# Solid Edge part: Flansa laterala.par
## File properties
Author: ptcarter
Template: Ansimm.Par
Last saved by: Ionut
Revision: 47
Application: Solid Edge
Accuracy: 0.99
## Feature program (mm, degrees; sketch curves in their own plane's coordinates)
sketch for "ExtrudedProtrusion_1" plane through (0, 0, 0) normal (0, 0, 1) x-axis (1, 0, 0)
  line (-45, -35) -> (-45, 35)
  arc centre (-35, 35) radius 10 from (-45, 35) to (-35, 45) cw
  line (-35, 45) -> (35, 45)
  arc centre (35, 35) radius 10 from (35, 45) to (45, 35) cw
  line (45, 35) -> (45, -35)
  arc centre (35, -35) radius 10 from (45, -35) to (35, -45) cw
  line (35, -45) -> (-35, -45)
  arc centre (-35, -35) radius 10 from (-35, -45) to (-45, -35) cw
extrude "ExtrudedProtrusion_1" add finite 10 along +normal
sketch for "Hole_1" plane through (0, 0, 10) normal (0, 0, 1) x-axis (1, 0, 0)
  hole centre (-35, -35) bore radius 5
hole "Hole_1" through
sketch for "Hole_2" plane through (0, 0, 10) normal (0, 0, 1) x-axis (1, 0, 0)
  hole centre (-35, 35) bore radius 5
hole "Hole_2" through
sketch for "Hole_3" plane through (0, 0, 10) normal (0, 0, 1) x-axis (1, 0, 0)
  hole centre (35, 35) bore radius 5
hole "Hole_3" through
sketch for "Hole_4" plane through (0, 0, 10) normal (0, 0, 1) x-axis (1, 0, 0)
  hole centre (35, -35) bore radius 5
hole "Hole_4" nominal diameter 7.8125 through
pattern "unnamed Pattern 1" of "Hole_1", "Hole_2", "Hole_3", "Hole_4"
sketch for "unnamed Protrusion 1" plane through (0, 0, 10) normal (0, 0, 1) x-axis (1, 0, 0)
  line (-17.3205, -30) -> (17.3205, -30)
  line (17.3205, -30) -> (34.641, 0)
  line (34.641, 0) -> (17.3205, 30)
  line (17.3205, 30) -> (-17.3205, 30)
  line (-17.3205, 30) -> (-34.641, 0)
  line (-34.641, 0) -> (-17.3205, -30)
  dimension = 34.641
extrude "unnamed Protrusion 1" add finite 20 along +normal
fillet "Round_1" radius 4
fillet "Round_2" radius 2  Radii2 = 1.5 mm
sketch for "Hole_5" plane through (0, 0, 30) normal (0, 0, 1) x-axis (1, 0, 0)
  hole centre (0, 0) bore radius 19
hole "Hole_5" through
sketch for "unnamed RevolvedCutout 1" plane through (0, 0, 0) normal (1, 0, 0) x-axis (0, 1, 0)
  line (25, 30) -> (28, 28.9081)
revolve "unnamed RevolvedCutout 1" cut full turn 360 deg
sketch for "unnamed RevolvedProtrusion 1" plane through (0, 0, 0) normal (0, -1, 0) x-axis (1, 0, 0)
revolve "unnamed RevolvedProtrusion 1" add full turn 360 deg about sketch line (0, -57.15) -> (0, -79.0482)
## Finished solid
Body 1: solid body, 56 faces, 118 edges, 60 vertices.
  Faces by surface: cylinder 28, plane 16, torus 10, cone 1, sphere 1
  Edges by curve: circle 62, line 44, intersection 12
Bounding box of the edges (mm; curved faces can reach further): 90.000 x 90.000 x 50.000, from (-45, -45, -20) to (45, 45, 30).
Cylindrical faces by radius (mm): R1.5 x6, R2 x4, R4 x6, R5 x4, R10 x4, R16 x1, R19 x1, R27.5 x1, R32.5 x1
Conical faces (half-angle, radius in mm at the cone's reference point): 70 deg R25 x1
Toroidal faces (ring radius, tube radius in mm): R5.5 r1.5 x6, R8 r2 x4
Spherical faces by radius (mm): R30 x1
Planar faces by outward normal: +x 1, +y 2, +z 3, -x 1, -y 2, -z 3, oblique 4
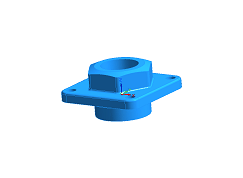
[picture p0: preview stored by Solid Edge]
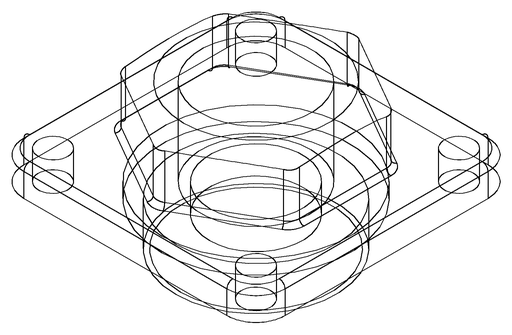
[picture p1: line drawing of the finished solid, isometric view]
